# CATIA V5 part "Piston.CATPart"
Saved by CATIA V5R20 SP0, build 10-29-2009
Part number: Piston
Material "Steel": density 7860 kg/m3, Young's modulus 2e+11 Pa, Poisson ratio 0.266, thermal expansion 1.17e-05 1/K
Bounding box of the stored display mesh (mm): x -50 to 50, y -49.993 to 49.993, z -35 to 50
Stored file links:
  E:\Ehsan\Amoozesh\CATIA\CATIA Course\Basic\Exercises\Assembly\12\Piston.CATPart
  D:\CATIA V5R20\B20\intel_a\startup\materials\Catalog.CATMaterial
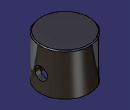
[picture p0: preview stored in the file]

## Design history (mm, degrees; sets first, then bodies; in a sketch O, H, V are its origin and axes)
Body1 (main body), material "Steel"
  Sketch1 on yz-plane, origin (0, 0, 0), H (0, 1, 0), V (0, 0, 1)
    line L1 (0, -35) -> (50, -35)
    line L2 (50, -35) -> (50, 50)
    line L3 (50, 50) -> (0, 50)
    axis line L4 (0, -38.6047) -> (0, 62.8046)
  Shaft1: profile Sketch1, axis Sketch1.L4, angle 360
  Shell1: IntOffset 10, Face face of Shaft1 from Sketch1.L1, ExtOffset 0
  Sketch2 on yz-plane, origin (0, 0, 0), H (0, 1, 0), V (0, 0, 1)
    circle A1 centre (0, 0) radius 12.5
  Pocket1: profile Sketch2, direction (-1, 0, 0), through (limit type 3), opposite side through (limit type 3)
  Chamfer1: length 2, angle 45, on face of Shaft1 from Sketch1.L3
